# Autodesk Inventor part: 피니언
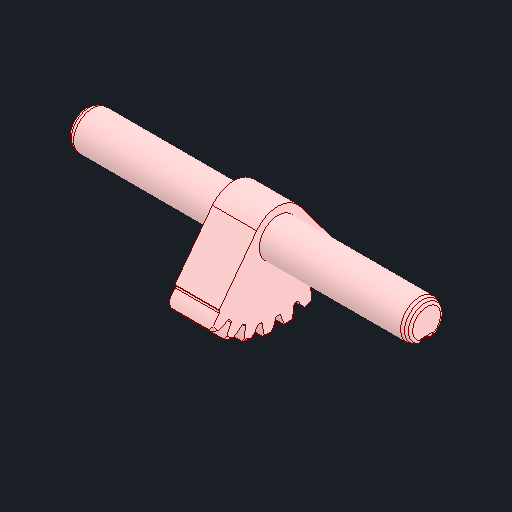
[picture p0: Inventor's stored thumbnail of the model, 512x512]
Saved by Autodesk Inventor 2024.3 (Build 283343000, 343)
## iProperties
Created: 2024-05
Part Number: 피니언
Material: 강철, 탄소
Document SubType Name: Modeling
Designer: MyPc
Density: 7.85 g/cm^3
Appearance: 기본값
Author: jhkim
Sending System: Autodesk Inventor 2025
Preprocessor: ST-DEVELOPER v20
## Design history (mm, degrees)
node "피니언1"
node "솔리드2"
node "솔리드1"
